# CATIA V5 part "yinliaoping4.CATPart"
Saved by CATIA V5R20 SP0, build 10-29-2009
Part number: 饮料瓶
Material "Multicoloured Flag"
Bounding box of the stored display mesh (mm): x -25 to 27, y -25 to 25, z 0 to 110
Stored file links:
  F:\0308\yinliaoping4.CATPart
  D:\study\catia\win_b64\startup\materials\Catalog.CATMaterial
  D:\study\catia\win_b64\startup\materials\chessboard.jpg
  D:\study\catia\win_b64\startup\materials\DS_star.jpg
  D:\study\catia\win_b64\startup\materials\solar_panel.jpg
  D:\study\catia\win_b64\startup\materials\sunset.jpg
  D:\study\catia\win_b64\startup\materials\summer_sky.jpg
  D:\study\catia\win_b64\startup\materials\raw_polystyren.jpg
  D:\study\catia\win_b64\startup\materials\strip_wall.jpg
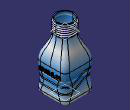
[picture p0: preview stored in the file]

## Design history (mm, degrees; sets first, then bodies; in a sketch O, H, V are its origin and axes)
Set1
  Sketch1 on xy-plane, origin (0, 0, 0), H (1, 0, 0), V (0, 1, 0)
    line L1 (25, 25) -> (25, -25)
    line L2 (25, -25) -> (-25, -25)
    line L3 (-25, -25) -> (-25, 25)
    line L4 (-25, 25) -> (25, 25)
    distance L2 L4 = 50
    distance L1 L3 = 50
    vertical: L1 V, L3 V
    horizontal: L2 H, L4 H
    equidistance: L1 L3 O, L2 L4 O
  Sketch2 on face of Pad1 from Sketch1.L2, origin (0, -25, 0), H (1, 0, 0), V (0, 0, 1)
    spline S1 through (-30, 20) (-10, 30) (10, 20) (30, 20)
  Extrude1: Element1 Sketch2, Lim1 20, Lim2 60
  Sketch3 on face of Pad1 from Sketch1.L2, origin (0, -25, 0), H (1, 0, 0), V (0, 0, 1)
    spline S1 through (-30, 30) (-10, 40) (10, 30) (30, 30)
  Extrude2: Element1 Sketch3, Lim1 56, Lim2 56
  MultiSel1: CommonCtxFeats ({extract ExtractElem face of Pad1 from Sketch1.L2}; {extract ExtractElem face of Fillet1}; {extract ExtractElem face of Pad1 from Sketch1.L1}; {extract ExtractElem face of Fillet1}; {extract ExtractElem face of Pad1 from Sketch1.L4}; {extract ExtractElem face of Fillet1}; {extract ExtractElem face of Pad1 from Sketch1.L3}; {extract ExtractElem face of Fillet1})
  MultiSel2: CommonCtxFeats ({extract ExtractElem face of Pad1 from Sketch1.L3}; {extract ExtractElem face of Fillet1}; {extract ExtractElem face of Pad1 from Sketch1.L2}; {extract ExtractElem face of Fillet1}; {extract ExtractElem face of Pad1 from Sketch1.L1}; {extract ExtractElem face of Fillet1}; {extract ExtractElem face of Pad1 from Sketch1.L4}; {extract ExtractElem face of Fillet1})
  Join1: Elements ({intersect ToIntersect1 {extract ExtractElem face of Pad1 from Sketch1.L3}, ToIntersect2 Extrude1}; {intersect ToIntersect1 {extract ExtractElem face of Fillet1}, ToIntersect2 Extrude1}; {intersect ToIntersect1 {extract ExtractElem face of Pad1 from Sketch1.L2}, ToIntersect2 Extrude1}; {intersect ToIntersect1 {extract ExtractElem face of Fillet1}, ToIntersect2 Extrude1}; {intersect ToIntersect1 {extract ExtractElem face of Pad1 from Sketch1.L1}, ToIntersect2 Extrude1}; {intersect ToIntersect1 {extract ExtractElem face of Fillet1}, ToIntersect2 Extrude1}; {intersect ToIntersect1 {extract ExtractElem face of Pad1 from Sketch1.L4}, ToIntersect2 Extrude1}; {intersect ToIntersect1 {extract ExtractElem face of Fillet1}, ToIntersect2 Extrude1})
  Join2: Elements ({intersect ToIntersect1 {extract ExtractElem face of Pad1 from Sketch1.L2}, ToIntersect2 Extrude2}; {intersect ToIntersect1 {extract ExtractElem face of Fillet1}, ToIntersect2 Extrude2}; {intersect ToIntersect1 {extract ExtractElem face of Pad1 from Sketch1.L1}, ToIntersect2 Extrude2}; {intersect ToIntersect1 {extract ExtractElem face of Fillet1}, ToIntersect2 Extrude2}; {intersect ToIntersect1 {extract ExtractElem face of Pad1 from Sketch1.L4}, ToIntersect2 Extrude2}; {intersect ToIntersect1 {extract ExtractElem face of Fillet1}, ToIntersect2 Extrude2}; {intersect ToIntersect1 {extract ExtractElem face of Pad1 from Sketch1.L3}, ToIntersect2 Extrude2}; {intersect ToIntersect1 {extract ExtractElem face of Fillet1}, ToIntersect2 Extrude2})
  Plane1: type Normal, Curve Join2, RefPoint vertex [face of MultiSel1 | face of MultiSel1]
  Circle1: type CtrRad, Start 0, End 180, Center vertex [face of MultiSel1 | face of MultiSel1], Support Plane1, Radius 1, FirstDirection (1, 0, 0)
Body1 (main body), material "Multicoloured Flag"
  Pad1: profile Sketch1, direction (0, 0, 1), length 50
  Fillet1: on edge [face of Pad1 from Sketch1.L1 | face of Pad1 from Sketch1.L2]; edge [face of Pad1 from Sketch1.L4 | face of Pad1 from Sketch1.L1]; edge [face of Pad1 from Sketch1.L3 | face of Pad1 from Sketch1.L4]; edge [face of Pad1 from Sketch1.L2 | face of Pad1 from Sketch1.L3]
  Plane2: type Offset, RefPlane end face of Pad1, Offset 40, reversed
  Sketch4 on Plane2, origin (0, 0, 90), H (1, 0, 0), V (0, -1, 0)
    circle A1 centre (0, 0) radius 15
    radius A1 = 15
  Pad2: profile Sketch4, direction (0, 0, 1), length 20
  Fillet2: on edge [start face of Pad1 | face of Pad1 from Sketch1.L3]
  Sketch5 on end face of Pad1, origin (0, 0, 50), H (1, 0, 0), V (0, 1, 0)
    point P1 (25, 0)
    distance V P1 = 25
    coincidence: P1 H
  Sketch6 on start face of Pad2, origin (0, 0, 90), H (1, 0, 0), V (0, -1, 0)
    point P1 (15, 0)
    distance V P1 = 15
    coincidence: P1 H
  Sketch7 on face of Pad1 from Sketch1.L2, origin (0, -25, 0), H (1, 0, 0), V (0, 0, 1)
  Loft1: solid, Sections ({boundary Boundary {extract ExtractElem end face of Pad1}}; {boundary Boundary {extract ExtractElem start face of Pad2}}), StartFace end face of Pad1, EndFace start face of Pad2
  Slot1: profile Circle1, centre curve Join2
  Plane3: type Normal, Curve Join1, RefPoint vertex [face of MultiSel2 | face of MultiSel2]
  Circle2: type CtrRad, Start 0, End 180, Center vertex [face of MultiSel2 | face of MultiSel2], Support Plane3, Radius 1, FirstDirection (1, 0, 0)
  Slot2: profile Circle2, centre curve Join1
  Shell1: IntOffset 0.5, Face end face of Pad2, ExtOffset 0
  Point1: type OnSurface, Support face of Pad2 from Sketch4.A1, RefPoint Sketch6, Length 2, Direction (0, 0, 1)
  Helix1: Direction Z axis, RefPoint Point1, Pitch 3, Height 16, TaperAngle 0
  Point2: type OnCurve, Support Helix1, RefPoint Point1, Length 5
  Point3: type OnCurve, Support Helix1, RefPoint vertex of Helix1, Length -5
  Line1: type PtDir, RefPoint Point1, Direction (1, 0, 0), Start 0, End 5
  Line2: type PtDir, RefPoint vertex of Helix1, Direction (0, 1, 0), Start 0, End 5
  Body2
    Sketch8 on Plane2, origin (0, 0, 90), H (1, 0, 0), V (0, -1, 0)
      circle A1 centre (0, 0) radius 14
      radius A1 = 14
    Pad3: profile Sketch8, direction (0, 0, -1), length 30, mirrored extent
  Remove1: tool Body2
  Sketch9 on Plane2, origin (0, 0, 90), H (1, 0, 0), V (0, -1, 0)
    circle A1 centre (0, 0) radius 14
  Pocket1: profile Sketch9, direction (0, 0, 1), length 30
  Pocket2: profile Sketch9, direction (0, 0, 1), length 30
  Pocket3: profile Sketch9, direction (0, 0, 1), length 23
  Pocket4: profile Sketch9, direction (0, 0, 1), length 23
  Sketch10 on Plane2, origin (0, 0, 90), H (1, 0, 0), V (0, -1, 0)
    circle A1 centre (0, 0) radius 14.75
    radius A1 = 14.75
  Pad4: profile Sketch10, direction (0, 0, 1), length 20
  Sketch11 on Plane2, origin (0, 0, 90), H (1, 0, 0), V (0, -1, 0)
    circle A1 centre (0, 0) radius 14.5
    radius A1 = 14.5
  Sketch12 on Plane2, origin (0, 0, 90), H (1, 0, 0), V (0, -1, 0)
    circle A1 centre (0, 0) radius 13.5
    radius A1 = 13.5
  Pocket5: profile Sketch12, direction (0, 0, 1), length 30, mirrored extent
  Sketch13 on Plane2, origin (0, 0, 90), H (1, 0, 0), V (0, -1, 0)
    circle A1 centre (0, 0) radius 14.5
Body3
  Sketch14 on face of Pad1 from Sketch1.L1, origin (25, 0, 0), H (0, 1, 0), V (0, 0, 1)
    polyline C1
    polyline C2
    polyline C3
    polyline C4
    polyline C5
    polyline C6
    polyline C7
    polyline C8
    polyline C9
    polyline C10
    polyline C11
  Pad5: profile Sketch14, direction (1, 0, 0), length 2
  Connect1: Curve1 Line1, Point1 vertex of Line1, Tension1 1, Curve2 Helix1, Point2 Point2, Tension2 1
  Connect2: Curve1 Line2, Point1 vertex of Line2, Tension1 1, Curve2 Connect1, Point2 Point3, Tension2 1
  Plane4: type Normal, Curve Connect2, RefPoint vertex of Connect2
  Plane5: type Normal, Curve Connect2, RefPoint vertex of Connect1
  Circle3: type CtrRad, Start 0, End 180, Center vertex of Connect2, Support Plane4, Radius 1, FirstDirection (-1, 0, 0)
  Circle4: type CtrRad, Start 0, End 180, Center vertex of Connect1, Support Plane5, Radius 1, FirstDirection (0, -1, 0)
  Rib1: profile Circle3, centre curve Connect2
